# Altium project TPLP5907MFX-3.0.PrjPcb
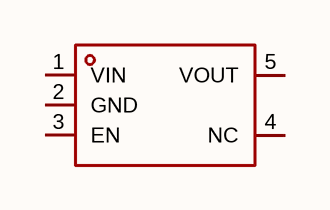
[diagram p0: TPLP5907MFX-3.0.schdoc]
1 sheet, 1 parts. Net scope: global (net labels, ports and power ports of the same name join across sheets).

## Sheet TPLP5907MFX-3.0.schdoc
size 127 x 101 mm

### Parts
U?  tplp5907mfx-3.0  [SOT-23-5_L2.9-W1.6-P0.95-LS2.8-BR]  (value not drawn)

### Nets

Not connected (* = marked no-connect by the designer): U? 1(VIN) 2(GND) 3(EN) 4(NC) 5(VOUT)

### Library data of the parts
U? = tplp5907mfx-3.0: 输出极性:正极;工作电压:5.5V;输出电压:3V;输出电流:300mA;电源纹波抑制比(PSRR):-;输出类型:固定;; Manufacturer: TECH PUBLIC(台舟); AddInBom: yes; ModelId: 7ba65df16e7b4570af156e925f9c37fe; ModelTransform: 114.173,114.173,0,90,0,0,0,0,0; Output Configuration: 正极; Voltage - Supply: 5.5V; Output Voltage: 3V; Output Current: 300mA; Voltage Dropout: 200mV@(300mA); standby current: 2uA; Output Type: 固定; Number of Outputs: 1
